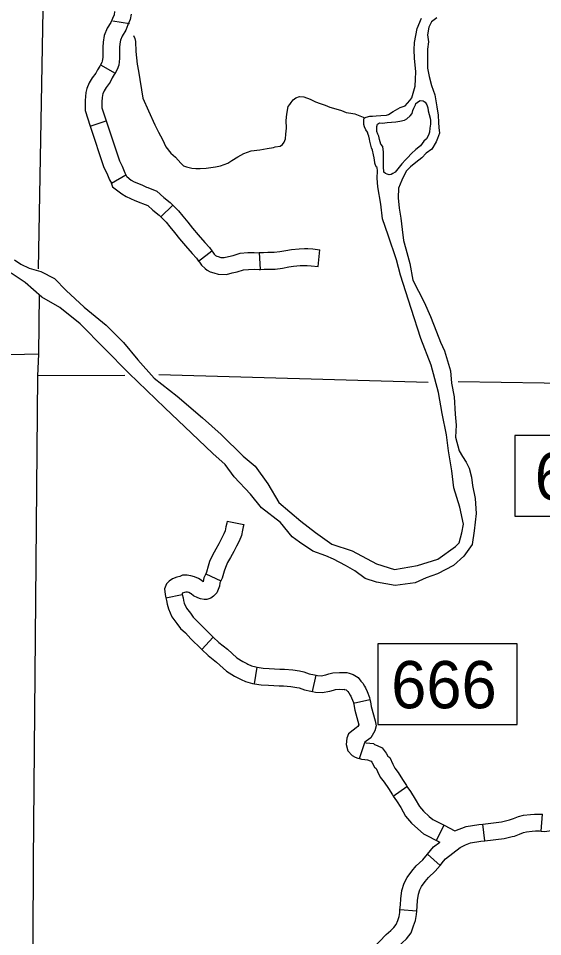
# Model space of a CAD drawing. Extents: x -492261 to -432772, y 1441225 to 1452922.
# Drawn here: x -464252.3 to -464118.7, y 1451078.9 to 1451313.1 of the extents above; entities that cross this region are included whole.
import ezdxf

# ---------------------------------------------------------------- set-up
doc = ezdxf.new("R2010")
doc.units = 0
doc.layers.add('Default', color=7, linetype='Continuous')

msp = doc.modelspace()

# ---------------------------------------------------------------- linework, layer by layer
at = {"layer": 'Default'}
for p, q in [((-464228.19, 1451312.51), (-464223.96, 1451311.81)), ((-464231.37, 1451301.28), (-464227.64, 1451299.18)), ((-464233.97, 1451285.63), (-464229.9, 1451286.97)), ((-464228.6, 1451271.09), (-464224.9, 1451273.25)), ((-464215.97, 1451262.49), (-464212.92, 1451265.5)), ((-464206.39, 1451251.23), (-464202.96, 1451253.8)), ((-464190.55, 1451249.11), (-464190.8, 1451253.39)), ((-464175.9, 1451249.86), (-464175.45, 1451254.12)), ((-464199.06, 1451184.9), (-464194.86, 1451184.01)), ((-464204.55, 1451171.47), (-464200.67, 1451169.67)), ((-464214.7, 1451165.34), (-464210.51, 1451166.22)), ((-464205.57, 1451152.2), (-464202.62, 1451155.31)), ((-464192.07, 1451143.42), (-464191.39, 1451147.65)), ((-464177.32, 1451141.42), (-464176.38, 1451145.6)), ((-464166.85, 1451138.48), (-464162.67, 1451139.42)), ((-464165.34, 1451124.34), (-464164.02, 1451128.42)), ((-464156.73, 1451114.76), (-464153.25, 1451117.25)), ((-464119.02, 1451105.87), (-464118.66, 1451110.14)), ((-464145.71, 1451103.5), (-464143.78, 1451107.33)), ((-464133.36, 1451103.4), (-464133.87, 1451107.66)), ((-464144.79, 1451097.12), (-464148.02, 1451099.93)), ((-464150.76, 1451085.39), (-464155.04, 1451085.74))]:
    msp.add_line(p, q, dxfattribs=at)
for points in [[(-464245.84, 1451464.67), (-464245.29, 1451378.93), (-464245.07, 1451371.95), (-464247.27, 1451249.26)], [(-464227.78, 1451314.87), (-464227.92, 1451314.03), (-464228.33, 1451313.09), (-464228.72, 1451312.09), (-464229.65, 1451310.63), (-464230.44, 1451308.79), (-464230.71, 1451307.08), (-464230.76, 1451305.79), (-464230.8, 1451303.67), (-464230.8, 1451303.15), (-464230.91, 1451302.23), (-464231.04, 1451301.88), (-464231.37, 1451301.28)], [(-464223.56, 1451314.17), (-464223.78, 1451312.81), (-464224.37, 1451311.46), (-464224.87, 1451310.15), (-464225.85, 1451308.62), (-464226.29, 1451307.59), (-464226.44, 1451306.65), (-464226.48, 1451305.66), (-464226.52, 1451303.66), (-464226.51, 1451302.92), (-464226.71, 1451301.21), (-464227.14, 1451300.07), (-464227.64, 1451299.18)], [(-464153.74, 1451290.79), (-464153.69, 1451290.82), (-464152.55, 1451292.19), (-464152.04, 1451292.82), (-464151.46, 1451294.65), (-464151.18, 1451295.85), (-464151.06, 1451297.62), (-464151, 1451299.51), (-464151.29, 1451302.94), (-464151.4, 1451305.12), (-464151.28, 1451306.95), (-464150.65, 1451310.55), (-464149.57, 1451313.18)], [(-464145.63, 1451313.24), (-464147, 1451312.27), (-464147.63, 1451310.84), (-464148.03, 1451308.89)], [(-464148.03, 1451308.89), (-464147.75, 1451307.18), (-464148.03, 1451305.29), (-464147.98, 1451302.66), (-464147.98, 1451300.43), (-464147.58, 1451298.31), (-464147.01, 1451296.02), (-464146.1, 1451293.62), (-464145.59, 1451290.59), (-464145.25, 1451288.41), (-464145.19, 1451286.58), (-464145.08, 1451285.32), (-464144.97, 1451283.89), (-464145.48, 1451282.46), (-464145.77, 1451281.66), (-464146.91, 1451279.78), (-464148.34, 1451278.75), (-464149.48, 1451277.55), (-464151.02, 1451276.4), (-464152.33, 1451275.26), (-464153.48, 1451274.17), (-464154.51, 1451271.83), (-464155.36, 1451269.83), (-464155.48, 1451267.37), (-464155.2, 1451264.73), (-464154.8, 1451262.16), (-464154.46, 1451259.3), (-464154.12, 1451256.5), (-464153.49, 1451254.32), (-464152.47, 1451250.61), (-464151.73, 1451246.37), (-464148.88, 1451240.77), (-464147.28, 1451237.1), (-464145.74, 1451233.21), (-464144.66, 1451230.58), (-464143.64, 1451228.35), (-464142.15, 1451223.2), (-464141.87, 1451220.06), (-464141.19, 1451216.57), (-464140.96, 1451212.16), (-464140.74, 1451209.42), (-464140.91, 1451206.33), (-464139.94, 1451202.84), (-464139.09, 1451201.41), (-464138.12, 1451199.98), (-464137.38, 1451198.43), (-464136.75, 1451196.15), (-464136.53, 1451194.03), (-464135.84, 1451190.71), (-464135.56, 1451186.88), (-464136.08, 1451182.42), (-464136.59, 1451178.93), (-464138.71, 1451176.01), (-464141.39, 1451173.55), (-464145.45, 1451171.44), (-464148.36, 1451170.47), (-464151.15, 1451169.21), (-464156.23, 1451168.52), (-464160.97, 1451169.32), (-464163.88, 1451170.3), (-464166.56, 1451172.24), (-464168.9, 1451173.62), (-464171.98, 1451175.22), (-464173.92, 1451176.08), (-464177.23, 1451177.28), (-464180.65, 1451179.57), (-464182.48, 1451180.89), (-464185.45, 1451184.55), (-464190.29, 1451188.27), (-464193.14, 1451191.76), (-464197.25, 1451196.22), (-464199.59, 1451199.37), (-464202.73, 1451202.11), (-464208.14, 1451207.32), (-464214.99, 1451213.78), (-464224.17, 1451222.6), (-464230.33, 1451228.89), (-464236.55, 1451235.24), (-464241.74, 1451239.36), (-464246.36, 1451242.05), (-464250.58, 1451245.77), (-464254.17, 1451248.17)], [(-464222.96, 1451308.74), (-464222.6, 1451307.97), (-464222.48, 1451307.23), (-464222.39, 1451304.65), (-464222.02, 1451301.45), (-464221.66, 1451299.63), (-464220.56, 1451292.77), (-464219.1, 1451289.53), (-464217.52, 1451286), (-464216.59, 1451284.12), (-464215.6, 1451282.19), (-464214.67, 1451280.37), (-464213.46, 1451278.78), (-464212.25, 1451277.71), (-464210.92, 1451276.23), (-464210.23, 1451275.5), (-464209.43, 1451275.22), (-464208.06, 1451274.95), (-464207.08, 1451274.85), (-464205.94, 1451274.8), (-464204.46, 1451274.88), (-464202.07, 1451275.25), (-464200.76, 1451275.49), (-464198.94, 1451276.2), (-464197.87, 1451276.84), (-464196.39, 1451277.83), (-464194.86, 1451278.65), (-464192.93, 1451279.36), (-464190.77, 1451279.61), (-464188.89, 1451279.92), (-464187.24, 1451280.22)], [(-464231.37, 1451301.28), (-464231.55, 1451300.96), (-464232.16, 1451299.96), (-464232.55, 1451299.11), (-464233.49, 1451297.93), (-464234.24, 1451296.67), (-464234.88, 1451295.28), (-464235.13, 1451294.2), (-464235.19, 1451293.2), (-464235.3, 1451292.16), (-464235.27, 1451289.59), (-464233.97, 1451285.63)], [(-464227.64, 1451299.18), (-464227.85, 1451298.79), (-464228.37, 1451297.95), (-464228.87, 1451296.85), (-464229.96, 1451295.49), (-464230.44, 1451294.67), (-464230.81, 1451293.88), (-464230.88, 1451293.58), (-464230.92, 1451292.86), (-464231.01, 1451291.95), (-464231, 1451290.3), (-464229.9, 1451286.97)], [(-464187.24, 1451280.22), (-464186.84, 1451280.4), (-464185.58, 1451280.53), (-464184.96, 1451280.99), (-464184.57, 1451281.51), (-464184.24, 1451282.43), (-464184.08, 1451283.63), (-464183.98, 1451285.12), (-464184, 1451287.12), (-464183.85, 1451288.73), (-464183.52, 1451290.62), (-464183.13, 1451291.19), (-464182.74, 1451291.71), (-464182.29, 1451292.35), (-464181.61, 1451292.87), (-464180.64, 1451293.23), (-464179.5, 1451293.12), (-464177.9, 1451292.51), (-464176.58, 1451291.84), (-464175.38, 1451291.4), (-464174.06, 1451291.01), (-464172.91, 1451290.51), (-464171.37, 1451290.07), (-464169.94, 1451289.63), (-464168.74, 1451289.13), (-464167.59, 1451288.97), (-464166.56, 1451288.81), (-464163.97, 1451287.73)], [(-464160.86, 1451275.06), (-464161.12, 1451275.26), (-464161.47, 1451276.18), (-464161.47, 1451276.35), (-464161.64, 1451277.55), (-464161.81, 1451278.35), (-464162.03, 1451279.49), (-464162.26, 1451280.12), (-464162.43, 1451280.75), (-464162.6, 1451281.5), (-464162.72, 1451281.78), (-464162.83, 1451282.35), (-464163, 1451283.04), (-464163.12, 1451283.5), (-464163.34, 1451284.07), (-464163.69, 1451284.7), (-464164.03, 1451285.5), (-464164.2, 1451286.02), (-464164.25, 1451286.36), (-464164.25, 1451286.53), (-464164.25, 1451287.1), (-464164.2, 1451287.5), (-464163.97, 1451287.73), (-464163.68, 1451287.96), (-464162.71, 1451288.19), (-464162.03, 1451288.19), (-464161.06, 1451288.25), (-464159.86, 1451288.36), (-464158.43, 1451288.47), (-464157.97, 1451288.65), (-464156.72, 1451289.39), (-464154.95, 1451290.42), (-464153.69, 1451290.82)], [(-464159.18, 1451279.04), (-464159.41, 1451280.47), (-464159.86, 1451281.04), (-464160.26, 1451282.24), (-464160.43, 1451283.04), (-464160.66, 1451283.56), (-464160.95, 1451284.24), (-464160.95, 1451284.36), (-464160.95, 1451284.93), (-464160.94, 1451285.56), (-464160.72, 1451286.13), (-464160.26, 1451286.47), (-464159.46, 1451286.42), (-464158.32, 1451286.53), (-464157.18, 1451286.64), (-464156.09, 1451286.76), (-464155.07, 1451286.87), (-464153.87, 1451287.16), (-464153.24, 1451287.5), (-464152.44, 1451288.24), (-464151.92, 1451288.87), (-464151.75, 1451289.62), (-464151.47, 1451290.19), (-464151.07, 1451291.05), (-464150.95, 1451291.45), (-464150.27, 1451291.96), (-464149.87, 1451292.19), (-464149.13, 1451292.08), (-464148.61, 1451291.79), (-464148.16, 1451291.05), (-464147.93, 1451290.3), (-464147.81, 1451289.56)], [(-464147.81, 1451289.56), (-464147.36, 1451287.67), (-464147.25, 1451287.04), (-464147.25, 1451286.18), (-464147.42, 1451285.1), (-464147.53, 1451284.07), (-464147.76, 1451283.32), (-464148.22, 1451282.41), (-464148.96, 1451281.78), (-464149.82, 1451280.64), (-464150.96, 1451279.72), (-464152.05, 1451278.69), (-464153.13, 1451277.55), (-464153.65, 1451277.03), (-464154.56, 1451276), (-464155.19, 1451275.2), (-464155.59, 1451274.75), (-464156.27, 1451273.94), (-464156.84, 1451273.54), (-464157.3, 1451273.32), (-464157.76, 1451273.26), (-464158.27, 1451273.37), (-464158.73, 1451273.6), (-464159.13, 1451273.89), (-464159.24, 1451275.38), (-464159.18, 1451276.86), (-464159.18, 1451279.04)], [(-464229.9, 1451286.97), (-464226.56, 1451276.82), (-464225.83, 1451275.44), (-464225.2, 1451273.77), (-464224.9, 1451273.25)], [(-464233.97, 1451285.63), (-464230.52, 1451275.13), (-464229.74, 1451273.67), (-464229.08, 1451271.92), (-464228.6, 1451271.09)], [(-464253.32, 1451251.55), (-464251.66, 1451250.46), (-464249.55, 1451249.43), (-464246.58, 1451248.57), (-464243.1, 1451246.8), (-464240.14, 1451243.71), (-464235.57, 1451239.47), (-464229.93, 1451234.84), (-464225.48, 1451230.43), (-464221.89, 1451226.03), (-464217.67, 1451221.39), (-464211.79, 1451216.76), (-464205.35, 1451211.21), (-464200.61, 1451206.97), (-464194.96, 1451201.48), (-464191.94, 1451198.91), (-464188.69, 1451194.44), (-464185.9, 1451189.64), (-464180.31, 1451184.89), (-464176.54, 1451182.03), (-464172.38, 1451179.05), (-464167.24, 1451177.33), (-464161.02, 1451174.02), (-464156.46, 1451172.58), (-464150.58, 1451173.55), (-464145.39, 1451175.21), (-464140.87, 1451178.47), (-464139.96, 1451179.33), (-464139.22, 1451181.9), (-464138.82, 1451184.13), (-464139.78, 1451188.48), (-464141.26, 1451193.4), (-464141.83, 1451197.75), (-464142.68, 1451202.84), (-464143.19, 1451206.9), (-464144.27, 1451212.34), (-464145.24, 1451217.71), (-464147.06, 1451224.69), (-464149.68, 1451231.5), (-464152.13, 1451239.17), (-464154.87, 1451247.63), (-464155.89, 1451251.52), (-464158.05, 1451257.87), (-464159.48, 1451261.99), (-464159.93, 1451265.71), (-464160.67, 1451270.17), (-464160.84, 1451272.34), (-464160.72, 1451274.23), (-464160.86, 1451275.06)], [(-464224.9, 1451273.25), (-464224.7, 1451272.92), (-464224.65, 1451272.77), (-464223.51, 1451271.9), (-464222.81, 1451271.47), (-464220.87, 1451270.64), (-464219.64, 1451270.08), (-464219.27, 1451269.98), (-464217.02, 1451269.07), (-464215.25, 1451267.46), (-464213.6, 1451266.18), (-464212.92, 1451265.5)], [(-464228.65, 1451271.18), (-464228.34, 1451270.19), (-464227.28, 1451269.38), (-464225.92, 1451268.35), (-464224.79, 1451267.66), (-464222.6, 1451266.71), (-464221.08, 1451266.04), (-464220.65, 1451265.92), (-464219.34, 1451265.39), (-464218.01, 1451264.17), (-464216.44, 1451262.96), (-464215.97, 1451262.49)], [(-464212.92, 1451265.5), (-464211.47, 1451264.04), (-464210.36, 1451262.7), (-464209.13, 1451261.15), (-464207.88, 1451259.59), (-464206.47, 1451257.93), (-464204.75, 1451255.96), (-464203.6, 1451254.65), (-464202.96, 1451253.8)], [(-464215.97, 1451262.49), (-464214.65, 1451261.15), (-464213.68, 1451259.99), (-464212.48, 1451258.48), (-464211.19, 1451256.86), (-464209.72, 1451255.13), (-464207.97, 1451253.13), (-464206.93, 1451251.95), (-464206.39, 1451251.23)], [(-464202.96, 1451253.8), (-464202.74, 1451253.5), (-464202.37, 1451253.01), (-464202.01, 1451252.65), (-464201.87, 1451252.56), (-464201.7, 1451252.46), (-464201.34, 1451252.37), (-464200.66, 1451252.16), (-464199.8, 1451252.14), (-464198.77, 1451252.43), (-464197.56, 1451252.67), (-464195.8, 1451253.24), (-464193.82, 1451253.4), (-464192.15, 1451253.42), (-464191.01, 1451253.37), (-464190.8, 1451253.39)], [(-464190.8, 1451253.39), (-464189.8, 1451253.44), (-464188.73, 1451253.46), (-464187.07, 1451253.47), (-464185.67, 1451253.64), (-464184.14, 1451253.93), (-464182.71, 1451254.2), (-464180.75, 1451254.34), (-464179.37, 1451254.42), (-464178.53, 1451254.43), (-464177.27, 1451254.32), (-464175.45, 1451254.12)], [(-464206.39, 1451251.23), (-464206.17, 1451250.94), (-464205.61, 1451250.19), (-464204.71, 1451249.3), (-464204.16, 1451248.94), (-464203.4, 1451248.48), (-464202.5, 1451248.24), (-464201.35, 1451247.89), (-464199.25, 1451247.84), (-464197.77, 1451248.26), (-464196.49, 1451248.51), (-464194.95, 1451249.01), (-464193.62, 1451249.11), (-464192.21, 1451249.13), (-464190.96, 1451249.08), (-464190.55, 1451249.11)], [(-464190.55, 1451249.11), (-464189.66, 1451249.16), (-464188.68, 1451249.17), (-464186.8, 1451249.19), (-464185.01, 1451249.4), (-464183.35, 1451249.72), (-464182.16, 1451249.94), (-464180.48, 1451250.07), (-464179.23, 1451250.14), (-464178.7, 1451250.14), (-464177.68, 1451250.05), (-464175.9, 1451249.86)], [(-464246.99, 1451242.68), (-464247.17, 1451227.46), (-464247.4, 1451221.97), (-464248.57, 1451098.13)], [(-464247.17, 1451227.46), (-464337.06, 1451225.37)], [(-464225.14, 1451222.02), (-464247.4, 1451221.97)], [(-464147.86, 1451220.29), (-464216.52, 1451222.19)], [(-464010.2, 1451215.05), (-464096.38, 1451219.76), (-464140.22, 1451220.46)], [(-464125.71, 1451186.21), (-464090.14, 1451186.21), (-464090.14, 1451206.76), (-464125.71, 1451206.76), (-464125.71, 1451186.21)], [(-464199.06, 1451184.9), (-464199.16, 1451184.41), (-464199.38, 1451183.47), (-464199.57, 1451182.46), (-464199.89, 1451181.64), (-464200.52, 1451180.5), (-464201.18, 1451179.14), (-464202, 1451177.75), (-464202.85, 1451176.19), (-464203.54, 1451174.57), (-464203.91, 1451173.42), (-464204.36, 1451171.88), (-464204.55, 1451171.47)], [(-464194.86, 1451184.01), (-464194.98, 1451183.47), (-464195.19, 1451182.57), (-464195.43, 1451181.28), (-464196, 1451179.81), (-464196.72, 1451178.53), (-464197.4, 1451177.13), (-464198.26, 1451175.64), (-464198.98, 1451174.32), (-464199.52, 1451173.07), (-464199.81, 1451172.15), (-464200.34, 1451170.36), (-464200.67, 1451169.67)], [(-464204.55, 1451171.47), (-464205.03, 1451170.44), (-464205.2, 1451169.48), (-464205.22, 1451169.44), (-464205.23, 1451169.44), (-464205.67, 1451169.83), (-464206.4, 1451170.27), (-464207.43, 1451170.74), (-464208.36, 1451170.98), (-464208.84, 1451171.04), (-464209.27, 1451171.13), (-464210.44, 1451171.11), (-464211.1, 1451170.82), (-464211.89, 1451170.6), (-464213.05, 1451170.17), (-464213.83, 1451169.6), (-464214.52, 1451168.89), (-464215.05, 1451167.62), (-464214.92, 1451166.17), (-464214.71, 1451165.36), (-464214.7, 1451165.34)], [(-464200.67, 1451169.67), (-464200.91, 1451169.15), (-464201.06, 1451168.28), (-464201.75, 1451166.59), (-464202.53, 1451165.79), (-464203.28, 1451165.28), (-464204.22, 1451164.95), (-464204.93, 1451164.94), (-464205.9, 1451165.11), (-464206.54, 1451165.31), (-464207.62, 1451165.84), (-464208.21, 1451166.36), (-464208.4, 1451166.48), (-464208.86, 1451166.68), (-464209.19, 1451166.77), (-464209.51, 1451166.81), (-464209.55, 1451166.82), (-464209.64, 1451166.78), (-464210.56, 1451166.52), (-464210.58, 1451166.51), (-464210.54, 1451166.35), (-464210.51, 1451166.22)], [(-464214.7, 1451165.34), (-464214.55, 1451164.62), (-464214.41, 1451163.72), (-464214.04, 1451162.5), (-464213.18, 1451160.48), (-464211.88, 1451158.82), (-464210.98, 1451157.55), (-464209.72, 1451156.38), (-464208.35, 1451154.92), (-464205.71, 1451152.34), (-464205.57, 1451152.2)], [(-464210.51, 1451166.22), (-464210.33, 1451165.38), (-464210.22, 1451164.68), (-464210.01, 1451163.96), (-464209.46, 1451162.68), (-464208.45, 1451161.39), (-464207.74, 1451160.39), (-464206.69, 1451159.41), (-464205.29, 1451157.92), (-464202.74, 1451155.42), (-464202.62, 1451155.31)], [(-464202.62, 1451155.31), (-464201.16, 1451153.92), (-464198.98, 1451152.24), (-464196.64, 1451150.05), (-464195.11, 1451149.08), (-464194.09, 1451148.56), (-464193.82, 1451148.46), (-464192.91, 1451148.01), (-464191.73, 1451147.71), (-464191.39, 1451147.65)], [(-464160.69, 1451133.06), (-464125.12, 1451133.06), (-464125.12, 1451153.61), (-464160.69, 1451153.61), (-464160.69, 1451133.06)], [(-464205.57, 1451152.2), (-464203.95, 1451150.67), (-464201.76, 1451148.97), (-464199.27, 1451146.64), (-464197.24, 1451145.36), (-464195.85, 1451144.65), (-464195.54, 1451144.53), (-464194.4, 1451143.97), (-464192.6, 1451143.51), (-464192.07, 1451143.42)], [(-464191.39, 1451147.65), (-464189.94, 1451147.42), (-464188.34, 1451147.33), (-464185.62, 1451147.19), (-464184.45, 1451147.14), (-464182.32, 1451146.99), (-464180.6, 1451146.7), (-464179.55, 1451146.5), (-464178.15, 1451145.99), (-464176.79, 1451145.69), (-464176.38, 1451145.6)], [(-464176.38, 1451145.6), (-464176.01, 1451145.52), (-464175.11, 1451145.49), (-464173.96, 1451145.67), (-464173.17, 1451145.95), (-464172.13, 1451146.18), (-464170.47, 1451146.34), (-464169.46, 1451146.29), (-464168.61, 1451146.3), (-464167.96, 1451146.09), (-464166.98, 1451145.8), (-464165.68, 1451145.02), (-464164.96, 1451144.13), (-464164.52, 1451143.56), (-464164.08, 1451142.82), (-464163.77, 1451142.36), (-464163.38, 1451141.45), (-464162.78, 1451139.9), (-464162.67, 1451139.42)], [(-464192.07, 1451143.42), (-464190.39, 1451143.15), (-464188.57, 1451143.05), (-464185.81, 1451142.91), (-464184.69, 1451142.87), (-464182.83, 1451142.73), (-464181.35, 1451142.48), (-464180.69, 1451142.35), (-464179.34, 1451141.86), (-464177.72, 1451141.51), (-464177.32, 1451141.42)], [(-464177.32, 1451141.42), (-464176.56, 1451141.25), (-464174.84, 1451141.19), (-464172.91, 1451141.5), (-464171.99, 1451141.82), (-464171.45, 1451141.94), (-464170.37, 1451142.04), (-464169.55, 1451142), (-464169.26, 1451142.01), (-464169.23, 1451141.99), (-464168.72, 1451141.84), (-464168.53, 1451141.73), (-464168.32, 1451141.48), (-464168.07, 1451141.15), (-464167.7, 1451140.52), (-464167.54, 1451140.3), (-464167.35, 1451139.84), (-464166.89, 1451138.66), (-464166.85, 1451138.48)], [(-464166.85, 1451138.48), (-464166.77, 1451138.1), (-464166.57, 1451136.72), (-464165.5, 1451132.98), (-464165.77, 1451132.5), (-464166.21, 1451132.17), (-464166.97, 1451131.58), (-464168.11, 1451130.7), (-464168.54, 1451129.59), (-464168.72, 1451127.94), (-464168.31, 1451126.36), (-464167.21, 1451125.17), (-464166.48, 1451124.74), (-464165.8, 1451124.49), (-464165.34, 1451124.34)], [(-464162.67, 1451139.42), (-464162.55, 1451138.86), (-464162.37, 1451137.61), (-464161.32, 1451133.96), (-464161.08, 1451132.73), (-464161.46, 1451131.43), (-464162.48, 1451129.6), (-464163.62, 1451128.76), (-464164.04, 1451128.43), (-464164.02, 1451128.42)], [(-464164.02, 1451128.42), (-464164, 1451128.41), (-464163.6, 1451128.38), (-464161.75, 1451128.21), (-464161.48, 1451127.94), (-464160.86, 1451127.72), (-464159.59, 1451127.05), (-464158.54, 1451125.74), (-464158.15, 1451124.97), (-464157.65, 1451124.61), (-464156.85, 1451122.88), (-464156.37, 1451121.9), (-464155.52, 1451120.81), (-464154.36, 1451119.01), (-464153.4, 1451117.47), (-464153.25, 1451117.25)], [(-464165.34, 1451124.34), (-464164.83, 1451124.18), (-464163.97, 1451124.11), (-464163.31, 1451124.05), (-464162.6, 1451123.79), (-464162.38, 1451123.67), (-464162.16, 1451123.4), (-464161.5, 1451122.12), (-464161.08, 1451121.81), (-464160.72, 1451121.03), (-464160.03, 1451119.62), (-464159.02, 1451118.33), (-464157.98, 1451116.72), (-464156.97, 1451115.08), (-464156.73, 1451114.76)], [(-464153.25, 1451117.25), (-464152.3, 1451115.93), (-464151.14, 1451114.01), (-464150.06, 1451112.12), (-464149.01, 1451110.9), (-464147.57, 1451109.59), (-464146.63, 1451108.77), (-464143.78, 1451107.33)], [(-464156.73, 1451114.76), (-464155.88, 1451113.56), (-464154.83, 1451111.84), (-464153.58, 1451109.64), (-464152.09, 1451107.91), (-464150.43, 1451106.4), (-464149.06, 1451105.19), (-464144.86, 1451103.07)], [(-464133.87, 1451107.66), (-464129.15, 1451108.22), (-464127.42, 1451108.61), (-464127.09, 1451108.69), (-464126.1, 1451109.06), (-464124.84, 1451109.58), (-464123.53, 1451109.89), (-464121.71, 1451110.1), (-464120.69, 1451110.17), (-464119.26, 1451110.19), (-464118.66, 1451110.14)], [(-464119.02, 1451105.87), (-464118.15, 1451105.79), (-464117, 1451105.88), (-464115.4, 1451106.1), (-464114.19, 1451106.47), (-464112.51, 1451107.13), (-464107.43, 1451108.87), (-464105.42, 1451109.46), (-464103.78, 1451109.95)], [(-464143.78, 1451107.33), (-464141.02, 1451105.94)], [(-464141.02, 1451105.94), (-464138.17, 1451107.06), (-464134.94, 1451107.53), (-464133.87, 1451107.66)], [(-464133.36, 1451103.4), (-464128.43, 1451103.99), (-464126.4, 1451104.44), (-464125.81, 1451104.6), (-464124.54, 1451105.06), (-464123.52, 1451105.48), (-464122.79, 1451105.66), (-464121.3, 1451105.83), (-464120.5, 1451105.89), (-464119.42, 1451105.9), (-464119.02, 1451105.87)], [(-464144.79, 1451097.12), (-464143.9, 1451098.15), (-464143.41, 1451098.78), (-464139.67, 1451101.65), (-464138.35, 1451102.38), (-464137.06, 1451102.89), (-464134.37, 1451103.28), (-464133.36, 1451103.4)], [(-464148.02, 1451099.93), (-464147.21, 1451100.87), (-464146.46, 1451101.84), (-464144.86, 1451103.07)], [(-464155.04, 1451085.74), (-464154.93, 1451087.03), (-464154.82, 1451088.59), (-464154.51, 1451090.72), (-464153.95, 1451092.57), (-464153.17, 1451094.02), (-464152, 1451095.66), (-464150.86, 1451096.96), (-464149.22, 1451098.56), (-464148.02, 1451099.93)], [(-464248.57, 1451098.13), (-464249.26, 1450920.52), (-464249.33, 1450917.03), (-464249.68, 1450874.66)], [(-464150.76, 1451085.39), (-464150.66, 1451086.71), (-464150.56, 1451088.13), (-464150.32, 1451089.79), (-464149.98, 1451090.91), (-464149.52, 1451091.76), (-464148.64, 1451092.99), (-464147.75, 1451094), (-464146.09, 1451095.62), (-464144.79, 1451097.12)], [(-464162.83, 1451074.75), (-464161.96, 1451075.91), (-464158.57, 1451079.47), (-464157.33, 1451080.54), (-464156.57, 1451081.27), (-464155.97, 1451082.03), (-464155.59, 1451083.05), (-464155.26, 1451084.06), (-464155.08, 1451085.13), (-464155.04, 1451085.74)], [(-464159.4, 1451072.18), (-464158.68, 1451073.14), (-464155.6, 1451076.37), (-464154.45, 1451077.37), (-464153.39, 1451078.37), (-464152.18, 1451079.91), (-464151.54, 1451081.65), (-464151.09, 1451083.04), (-464150.83, 1451084.61), (-464150.76, 1451085.39)]]:
    msp.add_lwpolyline(points, dxfattribs=at)
for points in [[(-464125.71, 1451186.21), (-464090.14, 1451186.21), (-464090.14, 1451206.76), (-464125.71, 1451206.76)], [(-464160.69, 1451133.06), (-464125.12, 1451133.06), (-464125.12, 1451153.61), (-464160.69, 1451153.61)]]:
    msp.add_lwpolyline(points, close=True, dxfattribs=at)

# ---------------------------------------------------------------- texts
for s, p in [('667', (-464120.67, 1451190.33)), ('666', (-464157.26, 1451137.17))]:
    msp.add_text(s, height=12.057, dxfattribs=at).set_placement(p)

doc.saveas('drawing.dxf')
